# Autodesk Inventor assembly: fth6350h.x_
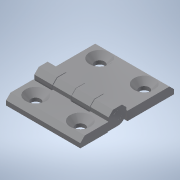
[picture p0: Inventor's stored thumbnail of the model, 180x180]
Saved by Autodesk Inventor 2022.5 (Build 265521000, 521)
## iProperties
Part Number: fth6350h.x_
Material: 一般
Document SubType Name: Assembly
Designer: ImaoCorp
Sending System: SOLIDWORKS 2017-2017317
MC: AMD64
MC_MODEL: Intel64 Family 6 Model 60 Stepping 3, GenuineIntel
OS: Windows_NT
FRU: Parasolid Version 29.0, build 201,  4-17-2017
FORMAT: text
GUISE: transmit
KEY: fth6350h
FILE: fth6350h.x_t
DATE: Mon May 13 14:28:26 2019
Author: ImaoCorp
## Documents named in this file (4)
- X:\14_SW2022-Inv2022\00_全2023-1023新製品(TCC)まで\f\fth6350h\FTH6350H.iam
- X:\14_SW2022-Inv2022\00_全2023-1023新製品(TCC)まで\f\fth6350h\fth6350h_01.ipt
- X:\14_SW2022-Inv2022\00_全2023-1023新製品(TCC)まで\f\fth6350h\fth6350h_02.ipt
- X:\14_SW2022-Inv2022\00_全2023-1023新製品(TCC)まで\f\fth6350h\fth6350h_03.ipt
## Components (3 placed, 3 different names)
1. fth6350h_01
2. fth6350h_02
3. fth6350h_03
